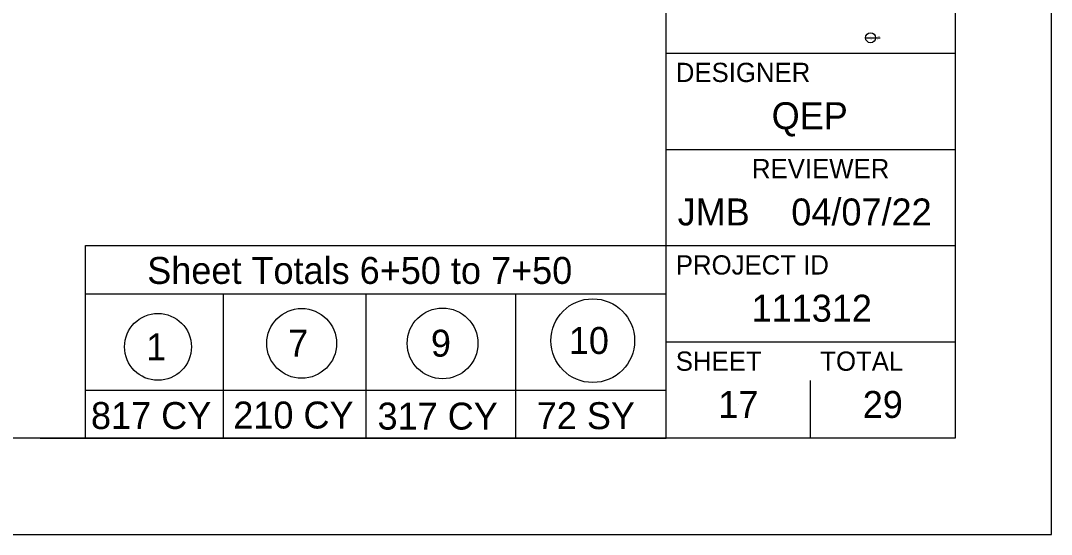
# Model space of a CAD drawing. Extents: x -179 to 34, y 0 to 22.
# Drawn here: x 28.65 to 34, y 0 to 2.67 of the extents above; entities that cross this region are included whole.
import ezdxf

# ---------------------------------------------------------------- set-up
doc = ezdxf.new("R2010")
doc.units = 0
for name, color, linetype in [('CS-ALGN-TEXT', 7, 'Continuous'), ('CS-ANNO', 7, 'Continuous'), ('CS-ANNO-MATC', 7, 'Continuous'), ('CS-ANNO-MATC-TEXT', 7, 'Continuous'), ('CS-ANNO-TABL', 7, 'Continuous')]:
    doc.layers.add(name, color=color, linetype=linetype)

msp = doc.modelspace()

# ---------------------------------------------------------------- linework, layer by layer
at = {"layer": 'CS-ALGN-TEXT'}
for p, q in [((28.9856, 0.5), (28.9856, 1.5)), ((28.9856, 1.5), (32, 1.5)), ((28.9856, 1.25), (32, 1.25)), ((29.7014, 0.5), (29.7014, 1.25)), ((30.4429, 0.5), (30.4429, 1.25)), ((31.2197, 0.5), (31.2197, 1.25)), ((28.9856, 0.75), (32, 0.75)), ((32.75, 0.5), (32.75, 0.8)), ((32.375, 0.675), (32.375, 0.675)), ((28.75, 0.5), (32, 0.5))]:
    msp.add_line(p, q, dxfattribs=at)
at = {"layer": 'CS-ANNO'}
msp.add_lwpolyline([(0, 0), (34, 0), (34, 22), (0, 22)], close=True, dxfattribs=at)
at = {"layer": 'CS-ANNO-MATC'}
for p, q in [((32, 0.5), (32, 21.5)), ((32, 2.5), (33.5, 2.5)), ((32, 2), (33.5, 2)), ((32, 1.5), (33.5, 1.5)), ((32, 1), (33.5, 1))]:
    msp.add_line(p, q, dxfattribs=at)
msp.add_lwpolyline([(1.5, 21.5), (33.5, 21.5), (33.5, 0.5), (1.5, 0.5)], close=True, dxfattribs=at)
at = {"layer": 'CS-ANNO-MATC-TEXT'}
for centre, radius in [((31.6189, 1.0064), 0.2175), ((29.3616, 0.9741), 0.1737), ((30.1077, 0.9923), 0.1813), ((30.8391, 0.9924), 0.1837)]:
    msp.add_circle(centre, radius, dxfattribs=at)
at = {"layer": 'CS-ANNO-TABL'}
for p, q in [((33.0353, 2.58), (33.0874, 2.58)), ((33.0616, 2.58), (33.111, 2.58))]:
    msp.add_line(p, q, dxfattribs=at)
msp.add_circle((33.0613, 2.58), 0.026, dxfattribs=at)

# ---------------------------------------------------------------- texts
at = {"layer": 'CS-ALGN-TEXT'}
for s, height, p in [('DESIGNER', 0.1, (32.05, 2.35)), ('QEP', 0.14, (32.5477, 2.105)), ('REVIEWER', 0.1, (32.4454, 1.85)), ('JMB', 0.14, (32.0596, 1.605)), ('04/07/22', 0.14, (32.6497, 1.605)), ('Sheet Totals 6+50 to 7+50', 0.14, (29.3058, 1.3012)), ('PROJECT ID', 0.1, (32.05, 1.35)), ('111312', 0.14, (32.4435, 1.105)), ('SHEET', 0.1, (32.05, 0.85)), ('TOTAL', 0.1, (32.8, 0.85)), ('17', 0.14, (32.2707, 0.605)), ('29', 0.14, (33.0206, 0.605))]:
    msp.add_text(s, height=height, dxfattribs=at).set_placement(p)
at = {"layer": 'CS-ANNO-MATC-TEXT'}
for s, p in [('10', (31.4948, 0.9373)), ('1', (29.3004, 0.9039)), ('7', (30.0376, 0.9232)), ('9', (30.7786, 0.9233)), ('817 CY', (29.0138, 0.5475)), ('210 CY', (29.7527, 0.5501)), ('317 CY', (30.5015, 0.5445)), ('72 SY', (31.328, 0.5468))]:
    msp.add_text(s, height=0.14, dxfattribs=at).set_placement(p)
at = {"layer": 'CS-ANNO-TABL'}
for s, p in [('7+00.00', (33.0533, 2.5701)), ('2', (33.0602, 2.5865)), ('1:2', (33.0941, 2.5701)), ('Drawing', (33.0941, 2.5865))]:
    msp.add_text(s, height=0.00328, dxfattribs=at).set_placement(p)

doc.saveas('drawing.dxf')
